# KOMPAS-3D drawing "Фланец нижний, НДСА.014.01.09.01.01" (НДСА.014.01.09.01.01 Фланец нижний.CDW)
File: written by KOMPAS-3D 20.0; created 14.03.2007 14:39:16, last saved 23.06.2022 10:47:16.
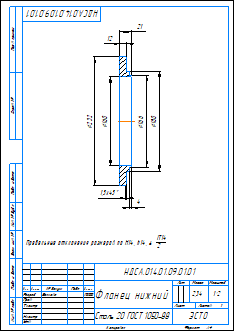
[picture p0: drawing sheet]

Sheet 1: A4, portrait

Document properties: Автор: Устинов А.В.; Организация: Эсто-вакуум; Полное имя файла: НДСА.014.01.09.01.01 Фланец нижний.m3d; 282871910340: <item xmlns="http://appius.ru/pdm" xmlns:xs="http://www.w3.org/2001/XMLSchema" xmlns:xsi="http://www.w3.org/2001/XMLSchema-instance" xsi:type="item">  <element xmlns:d2p1="http://v8.1c.ru/8.1/data/enterprise/current-config" xsi:type="d2p1:CatalogRef.aps_Элемен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; PLM_CDWXDTO: <item xmlns="http://appius.ru/pdm" xmlns:xs="http://www.w3.org/2001/XMLSchema" xmlns:xsi="http://www.w3.org/2001/XMLSchema-instance" xsi:type="item">  <element xmlns:d2p1="http://v8.1c.ru/8.1/data/enterprise/current-config" xsi:type="d2p1:CatalogRef.aps_Элемен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; Масса: 2.34227

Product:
- Part/product: Фланец нижний  | designation НДСА.014.01.09.01.01
    Материал: Сталь 20 ГОСТ 1050-88 (density 7859 kg/m3)
    Масса: 2.34227

Title block, sheet 1: Наименование: Фланец нижний; designation: НДСА.014.01.09.01.01; Материал: Сталь 20 ГОСТ 1050-88; Масса: 2,34; scale: 1:2; Количество листов документа: 1; organisation: ЭСТО; Форматы листов документа: A4; stored path: D:\Шлейф\УКРД.762.10.00.00.00 Верхняя стойка\УКРД.762.10.01.00.01 Фланец нижний.cdw; Разработал: Волкова; Разработал, date: 17.01.2020

Views: Вид 1, Сверху, Разрез А-А
Referenced files in E:\НДСА.014.01.09.00.00 Верхняя стойка гидроподъемника\: НДСА.014.01.09.01.01 Фланец нижний.m3d
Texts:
  НДСА.014.01.09.01.01 Фланец нижний
Dimensions and other numbers on the sheet: 160; 232; 166; 180; 21; 12; 4; 1,5; 1:2; 1; 2,34; 17.01.2020

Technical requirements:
  Предельные отклонения размеров по H14, h14,    IT14 2 .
